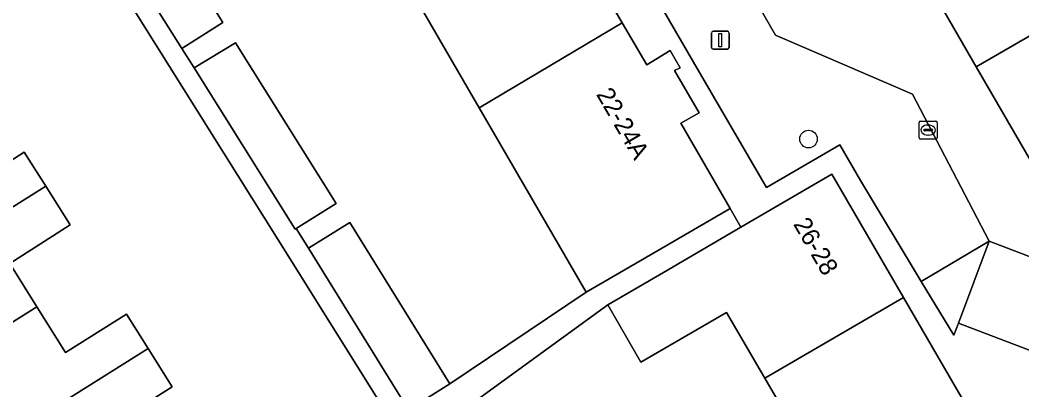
# Model space of a CAD drawing. Extents: x 161798 to 162385, y 382315 to 382833.
# Drawn here: x 162098.6 to 162154.5, y 382526.6 to 382547.2 of the extents above; entities that cross this region are included whole.
import ezdxf

# ---------------------------------------------------------------- set-up
doc = ezdxf.new("R2010")
doc.units = 0
for name, color, linetype in [('IMGEO_Boom', 7, 'Continuous'), ('IMGEO_Erf', 7, 'Continuous'), ('IMGEO_Kolk', 7, 'Continuous'), ('IMGEO_Lichtmast', 7, 'Continuous'), ('IMGEO_Pand', 7, 'Continuous'), ('IMGEO_Pand_nummerreeks', 7, 'Continuous'), ('IMGEO_Parkeervlak_open', 7, 'Continuous'), ('IMGEO_Verkeerseiland_open', 7, 'Continuous'), ('IMGEO_Voetpad_open', 7, 'Continuous'), ('IMGEO_Woonerf_open', 7, 'Continuous')]:
    doc.layers.add(name, color=color, linetype=linetype)

msp = doc.modelspace()

# ---------------------------------------------------------------- linework, layer by layer
at = {"layer": 'IMGEO_Boom'}
msp.add_circle((162142.591, 382540.541), 0.489, dxfattribs=at)
at = {"layer": 'IMGEO_Erf'}
for points in [[(162097.699, 382561.493), (162099.947, 382562.953), (162103.635, 382557.103), (162101.35, 382555.661), (162102.022, 382554.572), (162104.309, 382556.007), (162109.947, 382547.029), (162107.655, 382545.594), (162108.341, 382544.506), (162110.64, 382545.908), (162116.26, 382536.957), (162114.032, 382535.56), (162114.714, 382534.472), (162117.02, 382535.897), (162122.585, 382526.907), (162130.194, 382532.017), (162124.235, 382542.279), (162118.056, 382552.919), (162112.045, 382563.269), (162106.08, 382573.541), (162102.649, 382579.449), (162098.622, 382576.803)], [(162095.509, 382537.683), (162098.864, 382539.812), (162100.07, 382537.912), (162101.435, 382535.761), (162098.057, 382533.617), (162099.576, 382531.194), (162101.171, 382528.649), (162104.559, 382530.785), (162105.766, 382528.87), (162107.111, 382526.737), (162103.713, 382524.594), (162105.249, 382522.144), (162106.891, 382519.523), (162110.198, 382521.684), (162111.664, 382519.483), (162119.597, 382524.422), (162113.015, 382534.923), (162101.682, 382553.006), (162096.508, 382561.261)], [(162143.287, 382521.837), (162140.152, 382527.215), (162138.01, 382530.889), (162133.247, 382528.121), (162131.393, 382531.31), (162120.869, 382523.652)]]:
    msp.add_lwpolyline(points, dxfattribs=at)
at = {"layer": 'IMGEO_Kolk'}
for p, q in [((162148.759, 382540.619), (162148.759, 382541.471)), ((162148.834, 382541.545), (162149.686, 382541.545)), ((162149.018, 382541.039), (162149.018, 382541.051)), ((162149.061, 382541.088), (162149.459, 382541.088)), ((162149.247, 382541.325), (162149.272, 382541.325)), ((162149.502, 382541.051), (162149.502, 382541.039)), ((162149.76, 382541.471), (162149.76, 382540.619)), ((162149.686, 382540.545), (162148.834, 382540.545)), ((162149.456, 382541.002), (162149.058, 382541.002)), ((162149.27, 382540.765), (162149.245, 382540.765))]:
    msp.add_line(p, q, dxfattribs=at)
for points in [[(162148.759, 382540.619), (162148.759, 382541.471)], [(162148.834, 382541.545), (162149.686, 382541.545)], [(162149.76, 382541.471), (162149.76, 382540.619)], [(162149.686, 382540.545), (162148.834, 382540.545)]]:
    msp.add_lwpolyline(points, dxfattribs=at)
for centre, radius, start, end in [((162148.836, 382541.469), 0.0765, 91.552, 178.448), ((162148.836, 382541.469), 0.0765, 91.552, 178.448), ((162149.058, 382541.048), 0.0403, 85.8775, 175.7526), ((162149.055, 382541.038), 0.0366, 178.938, 274.7102), ((162149.459, 382541.045), 0.043, 264.8664, 352.4533), ((162149.463, 382541.05), 0.0386, 1.7309, 96.639), ((162149.684, 382541.469), 0.0765, 1.552, 88.448), ((162149.684, 382541.469), 0.0765, 1.552, 88.448), ((162148.836, 382540.621), 0.0765, 181.552, 268.448), ((162148.836, 382540.621), 0.0765, 181.552, 268.448), ((162149.684, 382540.621), 0.0765, 271.552, 358.448), ((162149.684, 382540.621), 0.0765, 271.552, 358.448)]:
    msp.add_arc(centre, radius, start, end, dxfattribs=at)
for centre, major_axis, ratio, start_param, end_param in [((162149.246, 382541.045), (-0.387, 0.002), 0.722429, 4.712389, 7.853982), ((162149.271, 382541.045), (-0.39, 0.002), 0.717154, 1.570796, 4.712389)]:
    msp.add_ellipse(centre, major_axis=major_axis, ratio=ratio, start_param=start_param, end_param=end_param, dxfattribs=at)
at = {"layer": 'IMGEO_Lichtmast'}
for p, q in [((162137.176, 382545.65), (162137.176, 382546.45)), ((162137.176, 382546.45), (162137.176, 382545.65)), ((162137.276, 382546.55), (162138.066, 382546.55)), ((162138.066, 382546.55), (162137.276, 382546.55)), ((162138.166, 382546.45), (162138.166, 382545.65)), ((162138.166, 382545.65), (162138.166, 382546.45)), ((162138.066, 382545.55), (162137.276, 382545.55)), ((162137.276, 382545.55), (162138.066, 382545.55))]:
    msp.add_line(p, q, dxfattribs=at)
msp.add_lwpolyline([(162137.596, 382546.425), (162137.746, 382546.425), (162137.746, 382545.675), (162137.596, 382545.675), (162137.596, 382546.425)], dxfattribs=at)
for centre, start, end in [((162137.276, 382546.45), 90, 180), ((162137.276, 382546.45), 90, 180), ((162138.066, 382546.45), 0, 90), ((162138.066, 382546.45), 360, 90), ((162137.276, 382545.65), 180, 270), ((162137.276, 382545.65), 180, 270), ((162138.066, 382545.65), 270, 0), ((162138.066, 382545.65), 270, 0)]:
    msp.add_arc(centre, 0.1, start, end, dxfattribs=at)
at = {"layer": 'IMGEO_Pand'}
for points in [[(162124.235, 382542.279), (162132.201, 382547.025), (162129.438, 382551.758), (162130.45, 382552.361), (162129.064, 382554.737), (162129.387, 382554.913), (162128.85, 382555.853), (162127.513, 382555.089), (162126.09, 382557.539), (162118.056, 382552.919)], [(162158.481, 382550.85), (162158.352, 382551.073), (162159.879, 382551.958), (162160.928, 382553.416), (162161.031, 382553.238), (162163.291, 382554.547), (162161.756, 382557.197), (162148.932, 382549.765), (162149.084, 382549.502), (162151.94, 382544.574), (162159.559, 382548.99)], [(162104.309, 382556.007), (162102.022, 382554.572), (162102.006, 382554.562), (162107.655, 382545.594), (162109.947, 382547.029)], [(162159.559, 382548.99), (162151.94, 382544.574), (162155.223, 382538.909), (162159.046, 382537.334), (162162.021, 382544.742)], [(162124.235, 382542.279), (162130.194, 382532.017), (162133.902, 382534.17), (162138.225, 382536.681), (162135.467, 382541.418), (162136.495, 382542.01), (162135.115, 382544.361), (162135.439, 382544.515), (162134.871, 382545.479), (162133.572, 382544.678), (162132.201, 382547.025)], [(162110.64, 382545.908), (162108.341, 382544.506), (162113.972, 382535.523), (162114.032, 382535.56), (162116.26, 382536.957)], [(162100.07, 382537.912), (162098.864, 382539.812), (162095.509, 382537.683), (162093.902, 382540.247), (162086.288, 382535.473), (162089.081, 382531.02)], [(162147.891, 382531.711), (162143.898, 382538.579), (162138.821, 382535.628), (162134.499, 382533.116), (162131.393, 382531.31), (162133.247, 382528.121), (162138.01, 382530.889), (162140.152, 382527.215)], [(162100.07, 382537.912), (162089.081, 382531.02), (162091.965, 382526.421), (162099.576, 382531.194), (162098.057, 382533.617), (162101.435, 382535.761)], [(162120.283, 382525.463), (162122.585, 382526.907), (162117.02, 382535.897), (162114.714, 382534.472)], [(162153.316, 382522.375), (162147.891, 382531.711), (162140.152, 382527.215), (162143.287, 382521.837)], [(162099.576, 382531.194), (162091.965, 382526.421), (162094.758, 382521.967), (162105.766, 382528.87), (162104.559, 382530.785), (162101.171, 382528.649)], [(162094.758, 382521.967), (162097.64, 382517.372), (162105.249, 382522.144), (162103.713, 382524.594), (162107.111, 382526.737), (162105.766, 382528.87)]]:
    msp.add_lwpolyline(points, close=True, dxfattribs=at)
at = {"layer": 'IMGEO_Parkeervlak_open'}
msp.add_lwpolyline([(162127.938, 382565.629), (162129.711, 382565.654), (162126.691, 382570.732), (162121.605, 382579.284), (162117.511, 382576.849), (162124.722, 382564.546), (162136.179, 382544.834), (162140.243, 382537.843), (162144.332, 382540.219), (162145.486, 382538.236), (162148.876, 382532.598), (162152.667, 382534.861), (162148.384, 382543.041), (162140.74, 382546.337), (162140.12, 382547.429), (162134.137, 382557.957), (162131.147, 382563.219)], dxfattribs=at)
msp.add_lwpolyline([(162158.702, 382531.126), (162159.178, 382532.372), (162152.667, 382534.861), (162150.943, 382530.295), (162157.436, 382527.813)], close=True, dxfattribs=at)
at = {"layer": 'IMGEO_Verkeerseiland_open'}
msp.add_lwpolyline([(162152.667, 382534.861), (162148.876, 382532.598), (162150.685, 382529.61), (162150.943, 382530.295)], close=True, dxfattribs=at)
at = {"layer": 'IMGEO_Voetpad_open'}
for points in [[(162154.834, 382522.502), (162156.392, 382526.576), (162156.895, 382526.399), (162157.436, 382527.813), (162150.943, 382530.295), (162150.685, 382529.61), (162148.876, 382532.598), (162145.486, 382538.236), (162144.332, 382540.219), (162140.243, 382537.843), (162136.179, 382544.834), (162124.722, 382564.546), (162117.511, 382576.849), (162116.346, 382578.064)], [(162096.508, 382561.261), (162101.682, 382553.006), (162113.015, 382534.923), (162119.597, 382524.422)], [(162120.869, 382523.652), (162131.393, 382531.31), (162134.499, 382533.116), (162138.821, 382535.628), (162138.225, 382536.681), (162133.902, 382534.17), (162130.194, 382532.017), (162122.585, 382526.907), (162120.283, 382525.463), (162114.714, 382534.472), (162114.032, 382535.56), (162113.972, 382535.523), (162108.341, 382544.506), (162107.655, 382545.594), (162102.006, 382554.562), (162102.022, 382554.572), (162101.35, 382555.661), (162097.699, 382561.493)], [(162129.438, 382551.758), (162132.201, 382547.025), (162133.572, 382544.678), (162134.871, 382545.479), (162135.439, 382544.515), (162135.115, 382544.361), (162136.495, 382542.01), (162135.467, 382541.418), (162138.225, 382536.681), (162138.821, 382535.628), (162143.898, 382538.579), (162147.891, 382531.711), (162153.316, 382522.375)]]:
    msp.add_lwpolyline(points, dxfattribs=at)
at = {"layer": 'IMGEO_Woonerf_open'}
msp.add_lwpolyline([(162139.134, 382557.41), (162134.69, 382565.121), (162131.147, 382563.219), (162134.137, 382557.957), (162140.12, 382547.429), (162140.74, 382546.337), (162148.384, 382543.041), (162152.667, 382534.861), (162159.178, 382532.372), (162160.799, 382536.612), (162159.046, 382537.334), (162155.223, 382538.909), (162151.94, 382544.574), (162149.084, 382549.502)], dxfattribs=at)

# ---------------------------------------------------------------- texts
at = {"layer": 'IMGEO_Pand_nummerreeks'}
for s, rotation, p in [('22-24A', 300.2127, (162130.729, 382543.036)), ('26-28', 300.1715, (162141.715, 382535.807))]:
    msp.add_text(s, height=1, rotation=rotation, dxfattribs=at).set_placement(p)

doc.saveas('drawing.dxf')
